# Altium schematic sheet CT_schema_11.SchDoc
size 391 x 238 mm
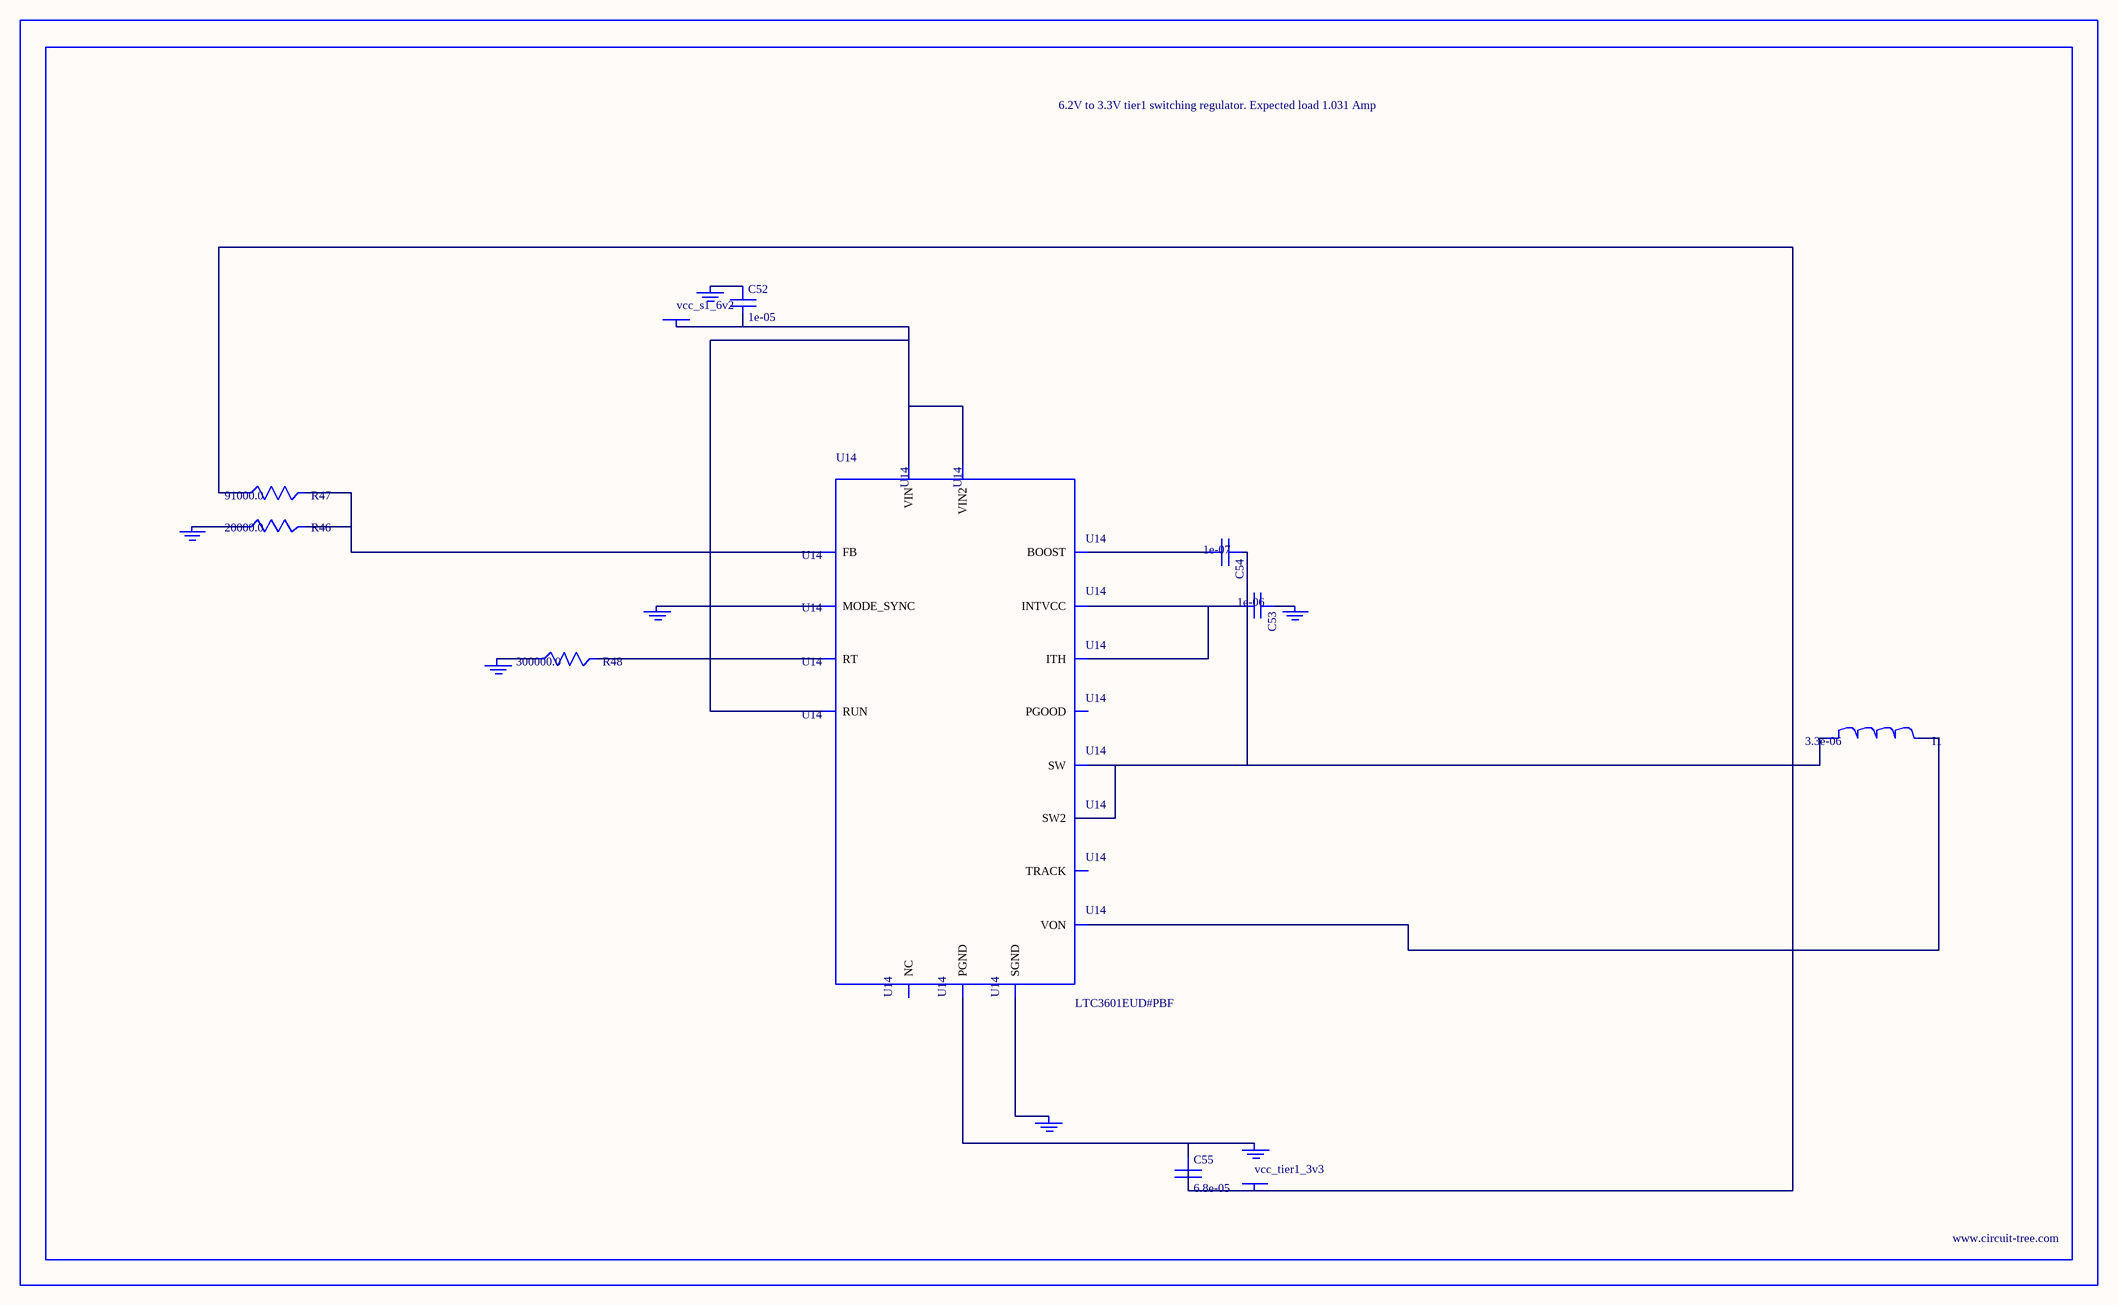
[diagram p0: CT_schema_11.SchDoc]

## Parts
BORDER10  (no value)
C52  1e-05  [C0805]
C53  1e-06  [C0603]
C54  1e-07  [C0402]
C55  6.8e-05  [2220]
GND_INSTANCE_10_0  (no value)
GND_INSTANCE_10_1  (no value)
GND_INSTANCE_10_2  (no value)
GND_INSTANCE_10_3  (no value)
GND_INSTANCE_10_4  (no value)
GND_INSTANCE_10_5  (no value)
GND_INSTANCE_10_6  (no value)
I1  3.3e-06  [WE-HCI_7030/7040/7050]
POWER_INSTANCE_10_0  vcc_s1_6v2
POWER_INSTANCE_10_1  vcc_tier1_3v3
R46  20000.0  [R0603]
R47  91000.0  [R0603]
R48  300000.0  [R0603]
U14  LTC3601EUD#PBF  [QFN-16_EP]

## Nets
NetC52_1: C52.1 GND_INSTANCE_10_5.0(GND)
NetC52_2: C52.2 POWER_INSTANCE_10_0.0(PWR) U14.14(RUN) U14.15(VIN) U14.16(VIN2)
NetC53_1: C53.1 GND_INSTANCE_10_1.0(GND)
NetC53_2: C53.2 U14.7(INTVCC) U14.12(ITH)
NetC54_1: C54.1 I1.1 U14.3(SW) U14.4(SW2)
NetC54_2: C54.2 U14.6(BOOST)
NetC55_1: C55.1 GND_INSTANCE_10_6.0(GND) U14.17(PGND)
NetC55_2: C55.2 I1.2 POWER_INSTANCE_10_1.0(PWR) R47.1 U14.8(VON)
NetGND_INSTANCE_10_0_0: GND_INSTANCE_10_0.0(GND) U14.1(MODE_SYNC)
NetGND_INSTANCE_10_2_0: GND_INSTANCE_10_2.0(GND) U14.9(SGND)
NetGND_INSTANCE_10_3_0: GND_INSTANCE_10_3.0(GND) R48.1
NetGND_INSTANCE_10_4_0: GND_INSTANCE_10_4.0(GND) R46.1
NetR46_2: R46.2 R47.2 U14.11(FB)
NetR48_2: R48.2 U14.10(RT)

Not connected (* = marked no-connect by the designer): U14 2(PGOOD) 5(NC) 13(TRACK)

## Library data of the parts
BORDER10 = BORDER_PAGE10
C52 = C0805C106K8RACTU
C53 = C0603C105K3RACTU
C54 = C0402C104K3RACTU
C55 = C5750X5R1A686M
GND_INSTANCE_10_0-GND_INSTANCE_10_6 = GND
I1 = 744314330
POWER_INSTANCE_10_0 POWER_INSTANCE_10_1 = PWR
R46 = RC0603JR-0720KL
R47 = RC0603JR-0791KL
R48 = RC0603JR-07300KL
